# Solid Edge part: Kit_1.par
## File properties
Sűrűség: 0,000 kg/m^3
Pontosság: 0,990
Author: bmolnar
Last saved by: bmolnar
Revision: 77
Username: bmolnar
Dokumentum tartalom típus: 0
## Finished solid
Body 1: solid body, 43 faces, 60 edges, 50 vertices.
  Faces by surface: cone 14, cylinder 14, plane 11, torus 4
  Edges by curve: circle 46, line 14
Bounding box of the edges (mm; curved faces can reach further): 55.000 x 54.575 x 5.500, from (-27.5, -25.9, 78.3) to (27.5, 28.675, 83.8).
Cylindrical faces by radius (mm): R1.25 x2, R2.5 x4, R8.27 x1, R8.85 x1, R10.16 x1, R10.25 x1, R17 x1, R23.975 x1, R25.9 x1, R27.5 x1
Conical faces (half-angle, radius in mm at the cone's reference point): 3 deg R10.205 x1, 7 deg R9.5925 x1, 14 deg R8.135 x1, 14 deg R8.4811 x1, 17 deg R8.135 x1, 23 deg R8.829 x1, 42.5 deg R8.1233 x1, 45 deg R9.1 x1, 45 deg R16.5 x1, 45 deg R25.8 x2, 84 deg R8.4608 x1, 85 deg R9.9463 x1, 87 deg R8.1765 x1
Toroidal faces (ring radius, tube radius in mm): R8.8057 r0.2025 x1, R9.2522 r0.2925 x1, R9.96 r0.2 x1, R17.8 r0.8 x1
Planar faces by outward normal: +z 6, -z 3, oblique 2
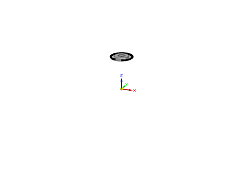
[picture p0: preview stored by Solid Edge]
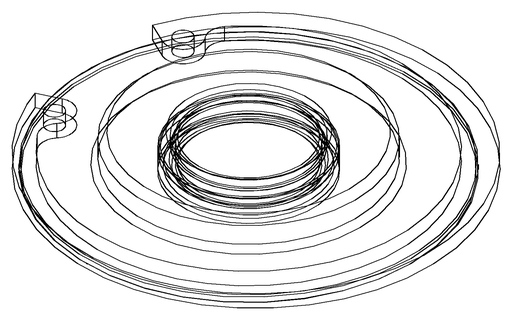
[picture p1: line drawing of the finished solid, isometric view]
